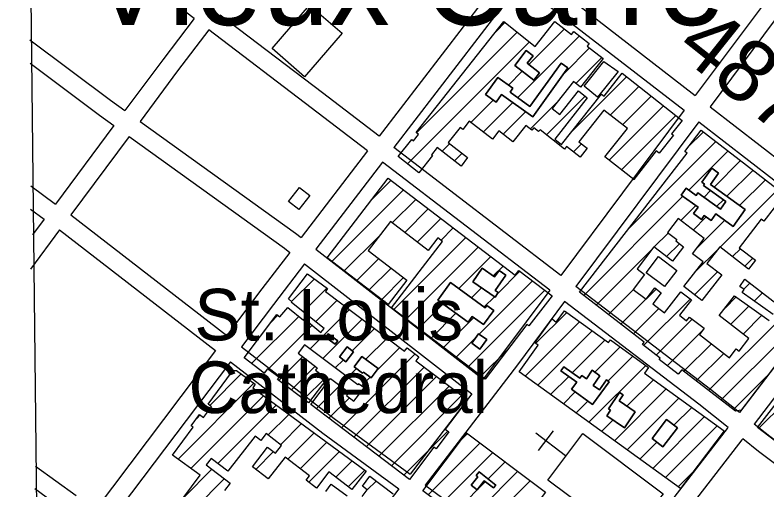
# Model space of a CAD drawing. Extents: x 3677843 to 3715951, y 511991 to 537744.
# Drawn here: x 3681900 to 3683108, y 532447 to 533211 of the extents above; entities that cross this region are included whole.
import ezdxf

# ---------------------------------------------------------------- set-up
doc = ezdxf.new("R2010")
doc.units = 0
for name, color, linetype in [('V-BLDG-OTLN', 7, 'Continuous'), ('V-GRID-FRAM', 7, 'Continuous'), ('V-ROAD-CNTR', 7, 'Continuous'), ('V-SITE-OTLN', 7, 'Continuous'), ('V-SITE-OTLN-IDEN', 7, 'Continuous'), ('V-SURV-IDEN', 7, 'Continuous'), ('V-TOPO-GNAM-IDEN', 7, 'Continuous')]:
    doc.layers.add(name, color=color, linetype=linetype)

msp = doc.modelspace()

# ---------------------------------------------------------------- linework, layer by layer
at = {"layer": 'V-BLDG-OTLN'}
for p, q in [((3682672.7, 533184.7), (3682686.9, 533198.9)), ((3682544.8, 533021.5), (3682706.7, 533183.3)), ((3682725.5, 533131.4), (3682782.6, 533188.6)), ((3682530.3, 532971.6), (3682726.5, 533167.8)), ((3682707.5, 533078.1), (3682806.9, 533177.5)), ((3682782.5, 533117.7), (3682822.9, 533158.1)), ((3682801.2, 533101.1), (3682842.7, 533142.5)), ((3682692.5, 533098.4), (3682714.6, 533120.5)), ((3682795, 533024.2), (3682882.5, 533111.7)), ((3682856.3, 533050.1), (3682902.3, 533096.1)), ((3682632.3, 533038.3), (3682668.1, 533074.1)), ((3682727.6, 533027.5), (3682770.9, 533070.8)), ((3682753.6, 533018.2), (3682815.9, 533080.4)), ((3682876.1, 533034.6), (3682922.1, 533080.6)), ((3682652.1, 533022.7), (3682699.6, 533070.2)), ((3682854.4, 532977.5), (3682941.9, 533065)), ((3682684.1, 533019.3), (3682720.2, 533055.4)), ((3682874.2, 532961.9), (3682961.7, 533049.4)), ((3682981.2, 532998.3), (3683006.1, 533023.1)), ((3682586.1, 532992), (3682598.4, 533004.3)), ((3682773.4, 533002.6), (3682775.4, 533004.5)), ((3682797, 532990.8), (3682810, 533003.8)), ((3682886.8, 532868.4), (3683026, 533007.7)), ((3682605.8, 532976.4), (3682618.2, 532988.8)), ((3682982.8, 532929.1), (3683046, 532992.3)), ((3683023.2, 532934.2), (3683065.9, 532976.9)), ((3683043.8, 532919.4), (3683085.9, 532961.5)), ((3682472.6, 532913.9), (3682503.7, 532945)), ((3682893.9, 532946.3), (3682895.1, 532947.5)), ((3683064.3, 532904.6), (3683105.8, 532946.1)), ((3682408.8, 532814.7), (3682523.8, 532929.7)), ((3683007.1, 532918), (3683017.6, 532928.6)), ((3683032.9, 532837.8), (3683125.7, 532930.6)), ((3682505.9, 532876.5), (3682543.8, 532914.4)), ((3682813.7, 532760), (3682973.1, 532919.4)), ((3683027.6, 532903.3), (3683038.2, 532913.8)), ((3682969.5, 532880.5), (3682993.6, 532904.6)), ((3682526, 532861.2), (3682563.8, 532899.1)), ((3682546, 532845.9), (3682583.9, 532883.8)), ((3682989.5, 532865.1), (3683010.6, 532886.2)), ((3682994, 532834.2), (3683040.5, 532880.8)), ((3682584, 532848.5), (3682603.9, 532868.5)), ((3682428.8, 532799.4), (3682485.8, 532856.4)), ((3682927, 532837.9), (3682949.4, 532860.4)), ((3682508.2, 532737.3), (3682624, 532853.1)), ((3682946.9, 532822.5), (3682967.6, 532843.2)), ((3682528.2, 532722), (3682644, 532837.8)), ((3682833.6, 532744.6), (3682924.5, 532835.4)), ((3682993.5, 532798.4), (3683029.6, 532834.5)), ((3683014.4, 532607.2), (3683243.3, 532836.1)), ((3683052.9, 532822.4), (3683065.6, 532835.1)), ((3682448.8, 532784.1), (3682484.1, 532819.3)), ((3682612.7, 532771.1), (3682664.1, 532822.5)), ((3683072.8, 532807), (3683085.5, 532819.7)), ((3682668.2, 532791.3), (3682684.1, 532807.2)), ((3682468.9, 532768.8), (3682504.1, 532804)), ((3682674.8, 532762.5), (3682711.2, 532798.9)), ((3682991.6, 532761.1), (3683028.6, 532798.2)), ((3682344, 532750), (3682380.8, 532786.7)), ((3682488.9, 532753.5), (3682524.2, 532788.7)), ((3682645.4, 532697.8), (3682731.2, 532783.6)), ((3682362.9, 532733.5), (3682400.9, 532771.5)), ((3682633.2, 532756.3), (3682649.3, 532772.4)), ((3682853.6, 532729.2), (3682893.7, 532769.3)), ((3682914.9, 532755.2), (3682930.1, 532770.3)), ((3683034.3, 532591.8), (3683222, 532779.5)), ((3683071.1, 532769.9), (3683080.9, 532779.8)), ((3682628.4, 532645.5), (3682751.2, 532768.3)), ((3682653.7, 532741.4), (3682670.2, 532757.9)), ((3683040.9, 532739.7), (3683058.6, 532757.5)), ((3683087.5, 532751), (3683100.9, 532764.4)), ((3682382.5, 532717.8), (3682417.1, 532752.4)), ((3682548.2, 532706.7), (3682587.8, 532746.3)), ((3682873.5, 532713.8), (3682913.7, 532753.9)), ((3682910, 532679.5), (3682984.7, 532754.2)), ((3682374, 532673.9), (3682437.3, 532737.2)), ((3682736.4, 532682.7), (3682786.3, 532732.6)), ((3682893.5, 532698.4), (3682934.3, 532739.2)), ((3683049.8, 532713.3), (3683079.3, 532742.8)), ((3682279.8, 532650.4), (3682355.6, 532726.2)), ((3682310.6, 532716.5), (3682322.1, 532728.1)), ((3682394.2, 532658.7), (3682457.4, 532721.9)), ((3682568.3, 532691.4), (3682608.3, 532731.4)), ((3682588.3, 532676.1), (3682636.8, 532724.5)), ((3682929.9, 532664.1), (3682987.9, 532722)), ((3683069.8, 532697.9), (3683100, 532728.1)), ((3682306.4, 532641.6), (3682376.9, 532712.1)), ((3682719.3, 532630.3), (3682806.8, 532717.8)), ((3682441.7, 532670.9), (3682477.6, 532706.7)), ((3682739.9, 532615.5), (3682827.3, 532702.9)), ((3682948, 532646.9), (3683004, 532702.9)), ((3682463.5, 532657.3), (3682497.7, 532691.5)), ((3682608.4, 532660.8), (3682641.1, 532693.5)), ((3682795.3, 532635.6), (3682847.8, 532688.1)), ((3682481.5, 532639.9), (3682517.9, 532676.3)), ((3682648.5, 532630.1), (3682692.5, 532674.2)), ((3682831.7, 532636.6), (3682872.3, 532677.2)), ((3682974.5, 532638), (3683018.8, 532682.3)), ((3682323.5, 532623.4), (3682361.6, 532661.5)), ((3682424.2, 532547.3), (3682542.8, 532665.9)), ((3682852.8, 532622.4), (3682892.8, 532662.3)), ((3682994.5, 532622.6), (3683038.7, 532666.8)), ((3682414.3, 532643.5), (3682427.3, 532656.5)), ((3683094.8, 532546.1), (3683205.4, 532656.8)), ((3682299.9, 532635.2), (3682301.2, 532636.4)), ((3682343.7, 532608.2), (3682381.8, 532646.3)), ((3682434.5, 532628.3), (3682448.6, 532642.4)), ((3682444.3, 532532), (3682557, 532644.8)), ((3682821.9, 532556.1), (3682913.3, 532647.5)), ((3682212.5, 532583.1), (3682263.1, 532633.7)), ((3682363.8, 532593), (3682398.5, 532627.7)), ((3682456.3, 532614.7), (3682470.3, 532628.7)), ((3682464.4, 532516.8), (3682577.1, 532629.5)), ((3682760.4, 532600.6), (3682789.5, 532629.7)), ((3682883, 532581.9), (3682925.7, 532624.5)), ((3683054.3, 532576.4), (3683108.2, 532630.2)), ((3682161.6, 532496.9), (3682283.5, 532618.8)), ((3682384, 532577.9), (3682421.6, 532615.4)), ((3682484.5, 532501.5), (3682597.3, 532614.3)), ((3682780.9, 532585.8), (3682800, 532604.9)), ((3682838.8, 532608.3), (3682839.3, 532608.8)), ((3682862.9, 532526.4), (3682946.2, 532609.7)), ((3682182, 532481.9), (3682298.8, 532598.6)), ((3682404.1, 532562.6), (3682437, 532595.5)), ((3682504.6, 532486.2), (3682617.4, 532599.1)), ((3682801.4, 532571), (3682820.4, 532589.9)), ((3682883.5, 532511.6), (3682966.7, 532594.8)), ((3682225.3, 532489.9), (3682319.2, 532583.7)), ((3682958.7, 532551.5), (3682987.2, 532580)), ((3682191.6, 532562.2), (3682197.1, 532567.7)), ((3682306.1, 532535.3), (3682339.6, 532568.7)), ((3682924.5, 532481.9), (3683007.7, 532565.1)), ((3682326.1, 532519.9), (3682360, 532553.8)), ((3682842.4, 532541.3), (3682860.7, 532559.5)), ((3682524.6, 532471), (3682595.3, 532541.6)), ((3682945, 532467.1), (3683028.2, 532550.3)), ((3682338.1, 532496.6), (3682380.4, 532538.8)), ((3682617.2, 532528.2), (3682627, 532537.9)), ((3682358.1, 532481.2), (3682400.8, 532523.9)), ((3682563.6, 532439.2), (3682647.1, 532522.8)), ((3682904, 532496.7), (3682931.2, 532523.9)), ((3682286.5, 532480.3), (3682315.1, 532508.9)), ((3682371.9, 532459.6), (3682421.2, 532508.9)), ((3682583.8, 532424), (3682667.3, 532507.6)), ((3682415.3, 532467.7), (3682441.6, 532494)), ((3682660, 532464.9), (3682687.5, 532492.4)), ((3682171.2, 532435.7), (3682215.9, 532480.4)), ((3682435.2, 532452.3), (3682462, 532479)), ((3682624.1, 532393.7), (3682707.7, 532477.2)), ((3682965.5, 532452.2), (3682988.3, 532475)), ((3682170.1, 532399.2), (3682235.9, 532465)), ((3682465.7, 532447.4), (3682479.8, 532461.5)), ((3682607.5, 532412.4), (3682655.6, 532460.5)), ((3682700.7, 532434.9), (3682727.9, 532462.1))]:
    msp.add_line(p, q, dxfattribs=at)
for points in [[(3682425.3, 533181.6), (3682365.1, 533111.8), (3682312.8, 533156.9), (3682373, 533226.7)], [(3682570.5, 532985.2), (3682548.5, 532957.3), (3682515.4, 532983.2), (3682537.1, 533010.7), (3682539.8, 533008.6), (3682548, 533019), (3682544.5, 533021.8), (3682685, 533200.4), (3682735.5, 533160.6), (3682767.1, 533200.8), (3682793.8, 533179.8), (3682797.7, 533184.7), (3682822.5, 533165.2), (3682819.2, 533161), (3682844.7, 533140.9), (3682808.7, 533095.1), (3682797.2, 533104.2), (3682763.1, 533060.9), (3682775.5, 533051.2), (3682805.1, 533088.8), (3682819.3, 533077.7), (3682767, 533011.1), (3682777.9, 533002.5), (3682842, 533083.9), (3682846.4, 533080.4), (3682875.4, 533117.3), (3682971.9, 533041.4), (3682955, 533019.9), (3682957.7, 533017.8), (3682934.8, 532988.7), (3682930.3, 532992.3), (3682894.1, 532946.2), (3682847.7, 532982.7), (3682883.8, 533028.5), (3682846.2, 533058.1), (3682806, 533007), (3682819.1, 532996.6), (3682807.8, 532982.3), (3682785.9, 532999.5), (3682782.6, 532995.4), (3682743.4, 533026.3), (3682741.2, 533023.5), (3682733.4, 533029.7), (3682730.1, 533025.6), (3682720.5, 533033.1), (3682699.9, 533006.8), (3682677.3, 533024.6), (3682666.8, 533011.2), (3682629.7, 533040.3), (3682619.1, 533026.8), (3682614.8, 533030.1), (3682596, 533006.2), (3682627.1, 532981.7), (3682616.4, 532968.1), (3682578.3, 532998.1), (3682569.1, 532986.3)], [(3682702.7, 533129.8), (3682721.3, 533153.7), (3682732.2, 533145.1), (3682723, 533133.3), (3682742.6, 533118), (3682733.2, 533106)], [(3682702.7, 533129.8), (3682733.2, 533106), (3682742.6, 533118), (3682723, 533133.3), (3682732.2, 533145.1), (3682721.3, 533153.7)], [(3682731.7, 533047.1), (3682681.7, 533083.1), (3682672.7, 533070.7), (3682655.7, 533083), (3682675.6, 533110.6), (3682699.7, 533093.3), (3682695.2, 533087), (3682727.2, 533063.9), (3682777.4, 533133.6), (3682788.3, 533125.8)], [(3682731.7, 533047.1), (3682788.3, 533125.8), (3682777.4, 533133.6), (3682727.2, 533063.9), (3682695.2, 533087), (3682699.7, 533093.3), (3682675.6, 533110.6), (3682655.7, 533083), (3682672.7, 533070.7), (3682681.7, 533083.1)], [(3682869.1, 533120.1), (3682835.8, 533079), (3682814.1, 533096.5), (3682846.2, 533136.3)], [(3683017.2, 532938.5), (3683073.4, 532898.1), (3683054, 532871.1), (3683026.2, 532891), (3683018.6, 532880.4), (3683007.3, 532888.6), (3683002.8, 532882.3), (3682990, 532891.6), (3682997.4, 532901.9), (3682970.4, 532921.3), (3682978.3, 532932.4), (3682994.2, 532920.9), (3682997.3, 532925.1), (3683033.6, 532899), (3683042.2, 532910.9), (3683006.4, 532936.7), (3683007.9, 532938.8), (3683003.6, 532941.9), (3683019.8, 532964.5), (3683030.4, 532956.8)], [(3683017.2, 532938.5), (3683030.4, 532956.8), (3683019.8, 532964.5), (3683003.6, 532941.9), (3683007.9, 532938.8), (3683006.4, 532936.7), (3683042.2, 532910.9), (3683033.6, 532899), (3682997.3, 532925.1), (3682994.2, 532920.9), (3682978.3, 532932.4), (3682970.4, 532921.3), (3682997.4, 532901.9), (3682990, 532891.6), (3683002.8, 532882.3), (3683007.3, 532888.6), (3683018.6, 532880.4), (3683026.2, 532891), (3683054, 532871.1), (3683073.4, 532898.1)], [(3682401.2, 532820.5), (3682499.1, 532948.6), (3682703.3, 532792.5), (3682709.3, 532800.3), (3682762.7, 532759.5), (3682725.5, 532710.9), (3682722.4, 532713.3), (3682655, 532625.1), (3682504.8, 532739.9), (3682586.4, 532846.7), (3682579, 532852.4), (3682563.7, 532832.4), (3682502.9, 532878.8), (3682467.3, 532832.1), (3682529.4, 532784.7), (3682499.4, 532745.5)], [(3682339.1, 532911.1), (3682356.7, 532933.6), (3682373.2, 532920.8), (3682355.6, 532898.2)], [(3682943.6, 532774.1), (3682914.1, 532796.6), (3682933.9, 532822.5), (3682963.3, 532800)], [(3682343.7, 532748.7), (3682344.5, 532749.6), (3682339.1, 532754.3), (3682369.8, 532795), (3682401.7, 532770.9), (3682398.4, 532766.5), (3682525.8, 532670.3), (3682529.8, 532675.7), (3682548.7, 532661.4), (3682543.7, 532654.8), (3682626.8, 532592.1), (3682591, 532544.8), (3682596.9, 532540.4), (3682576.3, 532513.1), (3682572.9, 532515.7), (3682533.8, 532464), (3682375, 532584.7), (3682406.8, 532626.6), (3682436.6, 532604), (3682432.6, 532598.8), (3682444.4, 532589.9), (3682460.7, 532611.4), (3682451.9, 532618), (3682450.5, 532616.1), (3682364.9, 532680.8), (3682354.4, 532666.9), (3682385.2, 532643.7), (3682382.4, 532639.9), (3682400.8, 532625.9), (3682371.5, 532587.2), (3682321.5, 532624.9), (3682324, 532628.2), (3682305.6, 532642.2), (3682300.1, 532635), (3682267.6, 532659.6), (3682320.4, 532729.5), (3682325.3, 532725.4), (3682337.9, 532740.8), (3682363.1, 532720), (3682364.9, 532722.1), (3682391.2, 532700.3), (3682396.3, 532706.7)], [(3682671.1, 532757.2), (3682676.3, 532764.8), (3682671.5, 532768.1), (3682688.5, 532792.6), (3682677.6, 532800.1), (3682670.4, 532789.8), (3682650.2, 532803.8), (3682635.2, 532782.1)], [(3682671.1, 532757.2), (3682635.2, 532782.1), (3682650.2, 532803.8), (3682670.4, 532789.8), (3682677.6, 532800.1), (3682688.5, 532792.6), (3682671.5, 532768.1), (3682676.3, 532764.8)], [(3682628.1, 532717.1), (3682634.6, 532726.1), (3682652.4, 532713.2), (3682668.9, 532735.9), (3682658, 532743.9), (3682655.4, 532740.3), (3682599.6, 532780.6), (3682579.2, 532752.5)], [(3682628.1, 532717.1), (3682579.2, 532752.5), (3682599.6, 532780.6), (3682655.4, 532740.3), (3682658, 532743.9), (3682668.9, 532735.9), (3682652.4, 532713.2), (3682634.6, 532726.1)], [(3682969, 532449.7), (3682709.7, 532637.3), (3682740.5, 532679.8), (3682734.9, 532683.8), (3682762.7, 532722.3), (3682769.6, 532717.2), (3682782.7, 532735.2), (3682853.4, 532684.1), (3682856.6, 532688.5), (3682918, 532644.1), (3682911.3, 532634.8), (3683039.4, 532542.2)], [(3682403, 532698.2), (3682398.9, 532692.6), (3682414.3, 532681.4), (3682418.4, 532687.1)], [(3682403, 532698.2), (3682418.4, 532687.1), (3682414.3, 532681.4), (3682398.9, 532692.6)], [(3682646.8, 532673.8), (3682657.7, 532689), (3682644.6, 532698.4), (3682633.7, 532683.1)], [(3682646.8, 532673.8), (3682633.7, 532683.1), (3682644.6, 532698.4), (3682657.7, 532689)], [(3682433.3, 532677.2), (3682421.1, 532661.2), (3682431.4, 532653.4), (3682443.5, 532669.5)], [(3682433.3, 532677.2), (3682443.5, 532669.5), (3682431.4, 532653.4), (3682421.1, 532661.2)], [(3682457.2, 532661.9), (3682483.4, 532642.5), (3682472.1, 532627.3), (3682459.5, 532636.7), (3682458.3, 532635.2), (3682444.8, 532645.2)], [(3682457.2, 532661.9), (3682444.8, 532645.2), (3682458.3, 532635.2), (3682459.5, 532636.7), (3682472.1, 532627.3), (3682483.4, 532642.5)], [(3683383.5, 532325.6), (3683092.8, 532547.7), (3683188.4, 532670.1), (3683240, 532629.8), (3683244.9, 532636), (3683334.1, 532566.2), (3683330.5, 532561.5), (3683476.9, 532447.2)], [(3682854.6, 532621.1), (3682827.6, 532584.6), (3682794.2, 532609.2), (3682802.4, 532620.5), (3682777, 532638.7), (3682781.6, 532645.2), (3682807.4, 532627), (3682810.5, 532631.3), (3682817.9, 532626.1), (3682827.4, 532639.7), (3682839.8, 532630.9), (3682828.8, 532615.4), (3682838.9, 532608.3), (3682850.2, 532624.3)], [(3682854.6, 532621.1), (3682850.2, 532624.3), (3682838.9, 532608.3), (3682828.8, 532615.4), (3682839.8, 532630.9), (3682827.4, 532639.7), (3682817.9, 532626.1), (3682810.5, 532631.3), (3682807.4, 532627), (3682781.6, 532645.2), (3682777, 532638.7), (3682802.4, 532620.5), (3682794.2, 532609.2), (3682827.6, 532584.6)], [(3682879.2, 532547), (3682850.7, 532566.4), (3682856.8, 532575.3), (3682853.4, 532577.6), (3682871.4, 532604), (3682877.1, 532600.1), (3682870.5, 532590.4), (3682896.6, 532572.6)], [(3682879.2, 532547), (3682896.6, 532572.6), (3682870.5, 532590.4), (3682877.1, 532600.1), (3682871.4, 532604), (3682853.4, 532577.6), (3682856.8, 532575.3), (3682850.7, 532566.4)], [(3682923.5, 532529.8), (3682946.8, 532560.5), (3682964.3, 532547.3), (3682941, 532516.5)], [(3682923.5, 532529.8), (3682941, 532516.5), (3682964.3, 532547.3), (3682946.8, 532560.5)], [(3682555.1, 532445.6), (3682625.4, 532539.1), (3682752.1, 532443.8), (3682680.3, 532348.4), (3682662.5, 532361.8), (3682667.2, 532368), (3682654.3, 532377.7), (3682651, 532373.4), (3682620.1, 532396.7), (3682623.1, 532400.7), (3682589.9, 532425.6), (3682587, 532421.7)], [(3682884.3, 532366.8), (3682756.2, 532463.1), (3682812.4, 532537.9), (3682941.4, 532441), (3682935.5, 532433.2), (3682946.1, 532425.2), (3682900.5, 532364.5), (3682889.1, 532373.1)], [(3682645.6, 532476.1), (3682641, 532470.2), (3682643.3, 532468.4), (3682632.8, 532454.9), (3682642.5, 532447.4), (3682653.8, 532461.9), (3682668.8, 532450.3), (3682672.5, 532455.1)], [(3682645.6, 532476.1), (3682672.5, 532455.1), (3682668.8, 532450.3), (3682653.8, 532461.9), (3682642.5, 532447.4), (3682632.8, 532454.9), (3682643.3, 532468.4), (3682641, 532470.2)]]:
    msp.add_lwpolyline(points, close=True, dxfattribs=at)
for points in [[(3683257.2, 532825.5), (3683066.5, 532575.6), (3683057.5, 532573.9), (3682971.1, 532640.6), (3682965.5, 532633.3), (3682934.8, 532657), (3682936.4, 532659.1), (3682908, 532681), (3682910.9, 532684.9), (3682807, 532765.2), (3682979.8, 532988.8), (3682976.1, 532991.6), (3683002.5, 533025.8), (3683136.3, 532922.5), (3683102.9, 532879.3), (3683098.9, 532882.4), (3683063.6, 532836.7), (3683089.5, 532816.6), (3683078.6, 532802.5), (3683032.4, 532838.2), (3683011.6, 532811.3), (3683035.4, 532792.9), (3683003.7, 532751.8), (3682974.8, 532774.2), (3683005.4, 532813.8), (3682988.4, 532827), (3683007.2, 532851.4), (3682965.4, 532883.7), (3682948.1, 532861.3), (3682963.2, 532849.7), (3682961.7, 532847.7), (3682973.9, 532838.3), (3682956.2, 532815.3), (3682926.6, 532838.2), (3682899.3, 532802.9), (3682911.6, 532793.4), (3682893.3, 532769.7), (3682913.8, 532753.8), (3682927.9, 532772), (3682938.2, 532764.1), (3682924.7, 532746.7), (3682943.6, 532732.1), (3682969.7, 532765.8), (3682986.7, 532752.7), (3682967.6, 532728.1), (3682978.9, 532719.3), (3682983.6, 532725.3), (3683007.3, 532707.1), (3682999.6, 532697.1), (3683047.7, 532659.9), (3683058.7, 532674.1), (3683063.5, 532670.4), (3683079.2, 532690.7), (3683031.5, 532727.5), (3683056, 532759.3), (3683111.5, 532719.9)], [(3683118.1, 532729.3), (3683068.1, 532764.8), (3683071.5, 532769.6), (3683064.5, 532774.6), (3683072.7, 532786.1), (3683124.8, 532745.9)], [(3682169.4, 532433.3), (3682197.1, 532470.7), (3682152.9, 532503.3), (3682186, 532548), (3682182.8, 532550.3), (3682196.1, 532568.3), (3682202.6, 532563.6), (3682215.4, 532580.9), (3682209.8, 532585), (3682247.4, 532635.9), (3682248.2, 532636.9), (3682249.2, 532637.7), (3682250.3, 532638.5), (3682251.5, 532639), (3682252.7, 532639.3), (3682254, 532639.5), (3682255.3, 532639.4), (3682285.8, 532617.1), (3682281.6, 532611.2), (3682464.1, 532477.5), (3682441.1, 532447.7), (3682404.2, 532476.2), (3682384.1, 532450.2), (3682367.5, 532463), (3682372.8, 532469.8), (3682333.6, 532500.1), (3682306.4, 532465), (3682281.1, 532484.5), (3682305.6, 532516.2), (3682318.4, 532506.3), (3682327.9, 532518.5), (3682303, 532537.7), (3682294.6, 532526.8), (3682285.6, 532533.7), (3682241.8, 532477.1), (3682215, 532497.9), (3682206.9, 532487.4), (3682245.2, 532457.8), (3682236.3, 532446.3)], [(3682457.7, 532436.4), (3682465.7, 532447.3), (3682457.8, 532453.2), (3682469.6, 532469.1), (3682507.6, 532441)], [(3682399, 532444.5), (3682407.8, 532456.5), (3682433.5, 532437.5)]]:
    msp.add_lwpolyline(points, dxfattribs=at)
at = {"layer": 'V-GRID-FRAM'}
msp.add_lwpolyline([(3681899.6, 535587.1), (3713561.2, 535950.9), (3713778.1, 517769.3), (3682100.6, 517405.3), (3681899.6, 535587.1)], dxfattribs=at)
at = {"layer": 'V-ROAD-CNTR'}
for points in [[(3682187.4, 533205.3), (3681920.6, 533408.8)], [(3683192, 533345.1), (3683113.1, 533242.9), (3682992.9, 533081.8)], [(3683215.7, 533326.7), (3683137, 533224.8), (3683016.7, 533063.5)], [(3682687.2, 533280.7), (3682484.6, 533016.1)], [(3682729.2, 533286.1), (3682992.9, 533081.8)], [(3682710.9, 533262.3), (3682508.4, 532997.9)], [(3682710.9, 533262.3), (3682975, 533057.8)], [(3682187.4, 533205.3), (3682136.9, 533139), (3682076.3, 533057.4)], [(3682484.6, 533016.1), (3682393.8, 533085.6), (3682229.4, 533211)], [(3682211.3, 533187.1), (3682160.9, 533121), (3682100.7, 533039.9)], [(3682466.3, 532992.3), (3682375.6, 533061.7), (3682211.3, 533187.1)], [(3681923.2, 533171), (3682052.9, 533074.2), (3682076.3, 533057.4)], [(3681923.7, 533133.3), (3682035.2, 533050), (3682058.4, 533033.3)], [(3683016.7, 533063.5), (3683258, 532876.5), (3683282.6, 532857.8)], [(3682975, 533057.8), (3682777.1, 532792.3)], [(3682100.7, 533039.9), (3682350.6, 532860), (3682359.6, 532853)], [(3682998.7, 533039.4), (3682800.9, 532774.1)], [(3682998.7, 533039.4), (3683239.8, 532852.7), (3683264.4, 532834)], [(3682058.4, 533033.3), (3681964.5, 532906.7)], [(3682082.8, 533015.8), (3681989.1, 532889.5)], [(3682082.8, 533015.8), (3682332.6, 532836), (3682341.4, 532829.1)], [(3682466.3, 532992.3), (3682359.6, 532853)], [(3682777.1, 532792.3), (3682508.4, 532997.9)], [(3682490.2, 532974.1), (3682383.3, 532834.5)], [(3682759.2, 532768.3), (3682490.2, 532974.1)], [(3681925, 532936), (3681964.5, 532906.7)], [(3681924.4, 532899), (3681946.6, 532882.6)], [(3681989.1, 532889.5), (3682240, 532695.6)], [(3681946.6, 532882.6), (3681927.9, 532857.4)], [(3681971.2, 532865.4), (3681924.3, 532802.4)], [(3681971.2, 532865.4), (3682221.9, 532671.6)], [(3682341.4, 532829.1), (3682291.1, 532763.5), (3682240, 532695.6)], [(3682383.3, 532834.5), (3682651.8, 532625.5)], [(3683264.4, 532834), (3683063.9, 532571.7)], [(3682365, 532810.7), (3682315, 532745.4), (3682263.7, 532677.3)], [(3682365, 532810.7), (3682633.6, 532601.7)], [(3683063.9, 532571.7), (3683017.3, 532608.6), (3682800.9, 532774.1)], [(3682759.2, 532768.3), (3682683.3, 532666.6), (3682651.8, 532625.5)], [(3682783, 532750.1), (3682707.2, 532648.5), (3682558.8, 532454.7)], [(3683045.6, 532547.8), (3682998.8, 532584.9), (3682783, 532750.1)], [(3682263.7, 532677.3), (3682412.5, 532562.2), (3682534.6, 532472.5)], [(3683186.2, 532682.3), (3683087.4, 532553)], [(3682221.9, 532671.6), (3682028.3, 532414.6)], [(3682245.7, 532653.3), (3682052.1, 532396.2)], [(3682245.7, 532653.3), (3682394.5, 532538.3), (3682516.4, 532448.7)], [(3682633.6, 532601.7), (3682534.6, 532472.5)], [(3683409.1, 532310.2), (3683112.7, 532533), (3683087.4, 532553)], [(3683045.6, 532547.8), (3683044.1, 532545.8), (3682823.6, 532260)], [(3683069.2, 532529.2), (3683067.9, 532527.5), (3682847.8, 532242.3)], [(3683391.1, 532286.3), (3683094.4, 532509.2), (3683069.2, 532529.2)], [(3681997.7, 532437.6), (3681932.7, 532485.1)], [(3682558.8, 532454.7), (3682823.6, 532260)], [(3681980.4, 532413.1), (3681931.2, 532449)], [(3682516.4, 532448.7), (3682318.2, 532189.9)]]:
    msp.add_lwpolyline(points, dxfattribs=at)
at = {"layer": 'V-SITE-OTLN'}
for p, q in [((3682764.6, 532542.2), (3682740.3, 532510.4)), ((3682784.2, 532502.1), (3682736.5, 532538.5))]:
    msp.add_line(p, q, dxfattribs=at)

# ---------------------------------------------------------------- texts
at = {"layer": 'V-SITE-OTLN-IDEN'}
for s, p in [('St. Louis', (3682187.9, 532687.6)), ('Cathedral', (3682178.5, 532570.8))]:
    msp.add_text(s, height=83, dxfattribs=at).set_placement(p)
at = {"layer": 'V-SURV-IDEN'}
msp.add_text('   487+35.7  ', height=100, rotation=321.4728, dxfattribs=at).set_placement((3682871.2, 533221.5))
at = {"layer": 'V-TOPO-GNAM-IDEN'}
msp.add_text('Vieux Carre', height=145, dxfattribs=at).set_placement((3682016.7, 533194.9))

doc.saveas('drawing.dxf')
